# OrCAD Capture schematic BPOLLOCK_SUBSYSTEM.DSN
size A; title: Stepper Motor Subsystem-Bradley Pollock; rev: 1; company: Bradley Pollock; note: 1
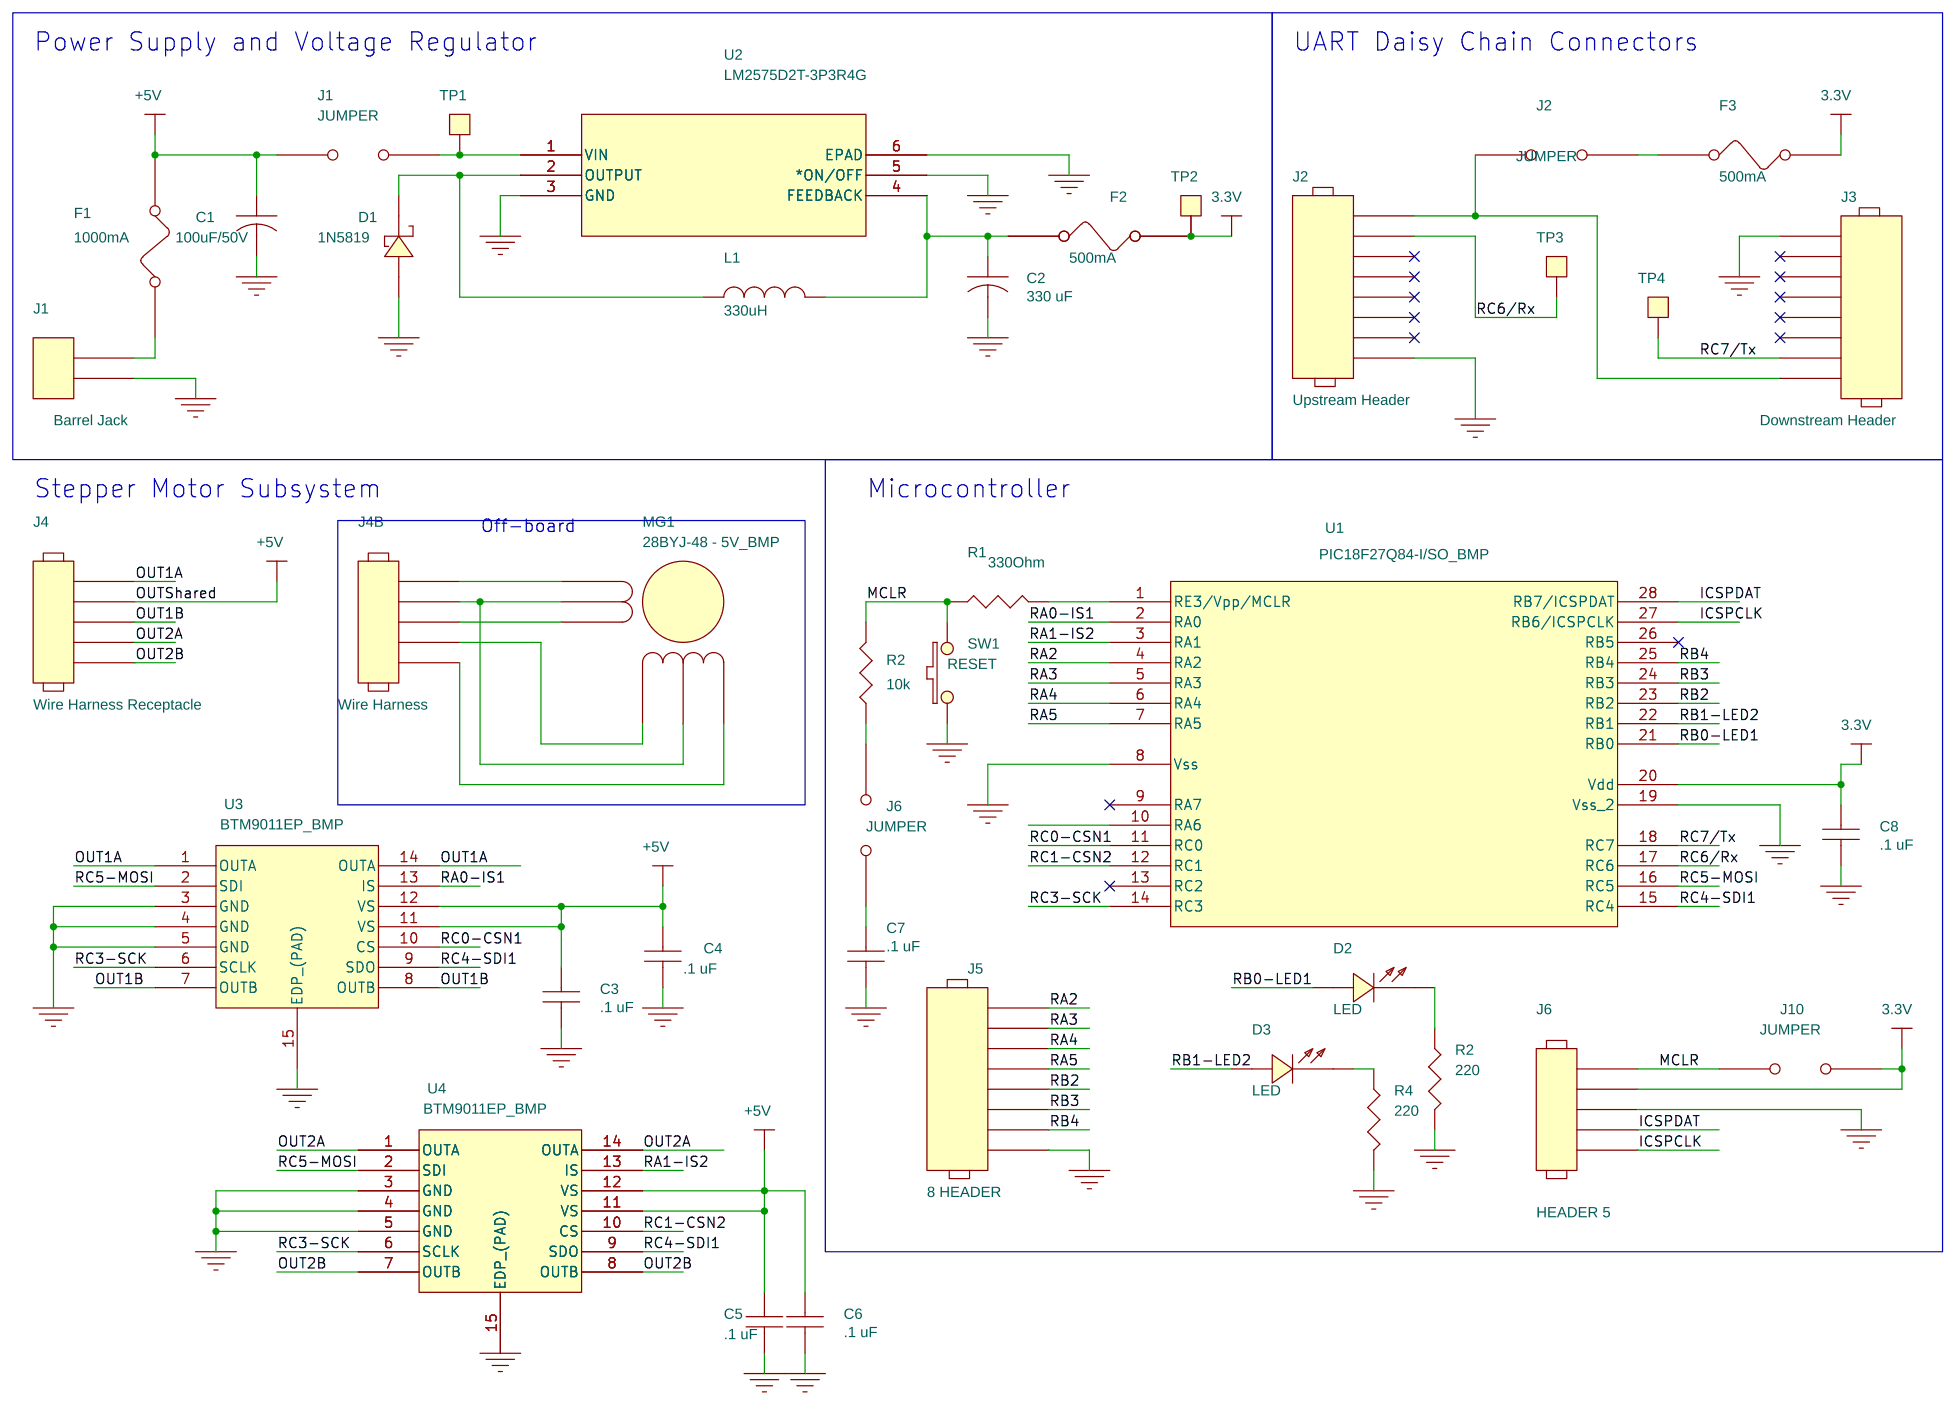
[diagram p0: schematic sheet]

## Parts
C1  100uF/50V
C2  330 uF
C3  .1 uF
C4  .1 uF
C5  .1 uF
C6  .1 uF
C7  .1 uF
C8  .1 uF
D1  1N5819
D2  LED
D3  LED
F1  1000mA
F2  500mA
F3  500mA
J1  JUMPER
J2  JUMPER
J3  Downstream Header
J4  Wire Harness Receptacle
J4B  Wire Harness
J5  8 HEADER
J6  HEADER 5
J10  JUMPER
L1  330uH
MG1  28BYJ-48 - 5V_BMP
R1  330Ohm
R2  10k
R2#2  10k
R4  220
SW1  RESET
TP1  T POINT S
TP2  T POINT S
TP3  T POINT S
TP4  T POINT S
U1  PIC18F27Q84-I/SO_BMP
U2  LM2575D2T-3P3R4G  [D2PAK-5_ONS]
U3  BTM9011EP_BMP
U4  BTM9011EP_BMP

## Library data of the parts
C1 C2 = CAP
C3-C8 = CAP_NP
D1 = DIODE_SCHOTTKY
D2 D3 = LED
F1-F3 = FUSE
J1 J2 J10 = JUMPER
J3 J5 = 8_HEADER
J4 J4B J6 = HEADER_5
L1 = INDUCTOR
MG1 = MOTOR_STEPPER
R1 R2 R2#2 R4 = R
SW1 = SW_PUSHBUTTON
TP1-TP4 = T_POINT_S
U1 = PIC18F27Q84-ISO_BMP
U2 = LM2575D2T-3P3R4G
U3 U4 = BTM9011EP_BMP

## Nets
3.3V: C8.1 F2.1 F3.1 J6.2 J10.2 R2#2.1 TP2.1(TP) U1.20(Vdd)
+5V: C1.1 C3.1 C4.1 C5.1 C6.1 F1.1 F1.2 J1.2 J4.2 U3.11(VS) U3.12(VS) U4.11(VS) U4.12(VS)
GND: C1.2 C2.2 C3.2 C4.2 C5.2 C6.2 C7.2 C8.2 D1.1(ANODE) J1.1 J2.8 J3.8 J5.8 J6.3 R2.2 R4.2 SW1.1 TP1.1(TP) U1.8(Vss) U1.19(Vss_2) U2.1(VIN) U2.3(GND) U2.5(*ON/OFF) U2.6(EPAD) U3.3(GND) U3.4(GND) U3.5(GND) U3.15(EDP_(PAD)) U4.3(GND) U4.4(GND) U4.5(GND) U4.15(EDP_(PAD))
ICSPCLK: J6.5 U1.27(RB6/ICSPCLK)
ICSPDAT: J6.4 U1.28(RB7/ICSPDAT)
MCLR: C7.1 J6.1 J10.1 R1.1 R2#2.2 SW1.2
OUT1A: J4.1 U3.1(OUTA) U3.14(OUTA)
OUT1B: J4.3 U3.7(OUTB) U3.8(OUTB)
OUT2A: J4.4 U4.1(OUTA) U4.14(OUTA)
OUT2B: J4.5 U4.7(OUTB) U4.8(OUTB)
RA0-IS1: U1.2(RA0) U3.13(IS)
RA1-IS2: U1.3(RA1) U4.13(IS)
RA2: J5.1 U1.4(RA2)
RA3: J5.2 U1.5(RA3)
RA4: J5.3 U1.6(RA4)
RA5: J5.4 U1.7(RA5)
RB0-LED1: D2.2(ANODE) U1.21(RB0)
RB1-LED2: D3.2(ANODE) U1.22(RB1)
RB2: J5.5 U1.23(RB2)
RB3: J5.6 U1.24(RB3)
RB4: J5.7 U1.25(RB4)
RC0-CSN1: U1.11(RC0) U3.10(CS)
RC1-CSN2: U1.12(RC1) U4.10(CS)
RC3-SCK: U1.14(RC3) U3.6(SCLK) U4.6(SCLK)
RC4-SDI1: U1.15(RC4) U3.9(SDO) U4.9(SDO)
RC5-MOSI: U1.16(RC5) U3.2(SDI) U4.2(SDI)
RC6/Rx: F3.2 J2.2 TP3.1(TP) U1.17(RC6)
RC7/Tx: J3.2 TP4.1(TP) U1.18(RC7)
N02724: D1.2(CATHODE) L1.1 U2.2(OUTPUT)
N02756: C2.1 F2.2 L1.2 U2.4(FEEDBACK)
N05235: J2.1 J3.1
N06953: R1.2 U1.1(RE3/Vpp/MCLR)
N09521: J4B.2 MG1.2 MG1.5
N13847: J4B.1 MG1.1
N13851: J4B.3 MG1.3
N13855: J4B.4 MG1.4
N13864: J4B.5 MG1.6
N15027: D2.1(CATHODE) R2.1
N15031: D3.1(CATHODE) R4.1

Not connected (* = marked no-connect by the designer): J2 3* 4* 5* 6* 7*; J3 3* 4* 5* 6* 7*; U1 9(RA7)* 10(RA6) 13(RC2)* 26(RB5)*

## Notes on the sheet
- Power Supply and Voltage Regulator
- UART Daisy Chain Connectors
- Stepper Motor Subsystem
- Microcontroller
- Off-board
